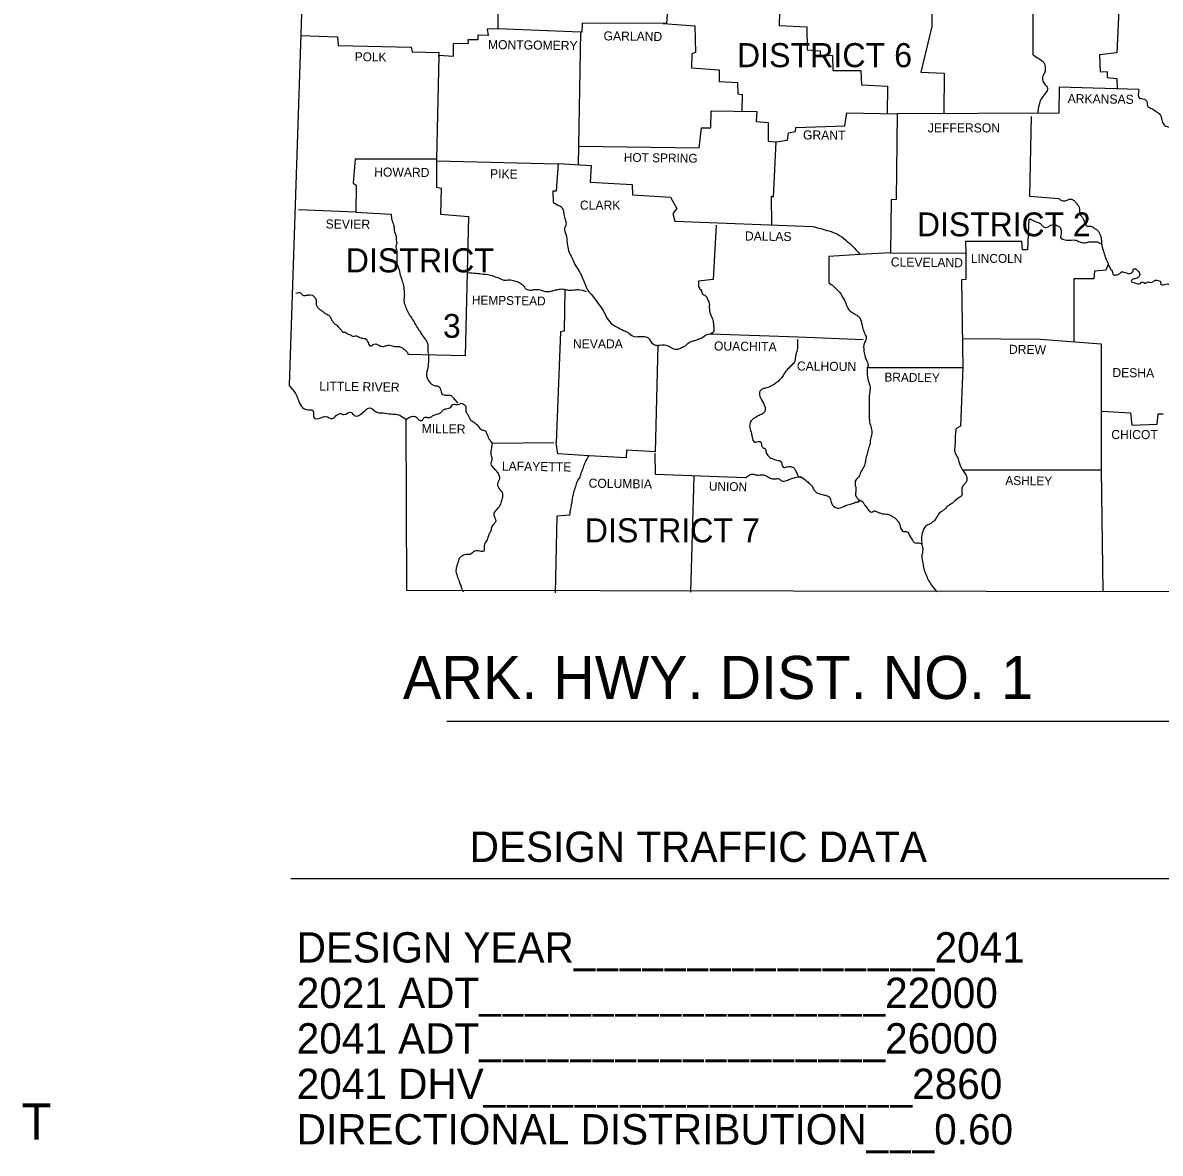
# Model space of a CAD drawing. Extents: x -117616 to 64730, y 54117 to 789866.
# Drawn here: x 63874 to 64437, y 55167 to 55726 of the extents above; entities that cross this region are included whole.
import ezdxf

# ---------------------------------------------------------------- set-up
doc = ezdxf.new("R2010")
doc.units = 0
doc.layers.add('Default', color=7, linetype='Continuous')
doc.layers.add('R_Draft', color=7, linetype='Continuous')

msp = doc.modelspace()

# ---------------------------------------------------------------- linework, layer by layer
at = {"layer": 'Default'}
for p, q in [((64150.16, 55721.35), (64148.95, 55655.78)), ((64084.07, 55380.58), (64442.95, 55380.58))]:
    msp.add_line(p, q, dxfattribs=at)
for points in [[(63993.86, 56003.36), (64015.47, 55829.83), (64006.07, 55546.57)], [(64109.44, 55783.99), (64109.23, 55722.91), (64104.01, 55722.81), (64104.43, 55719.68), (64099.42, 55719.78), (64099.31, 55717.49), (64094.41, 55717.49), (64094.51, 55715.81), (64087.2, 55715.61), (64087.1, 55709.24), (64080, 55709.86), (64078.85, 55658.49), (64038.65, 55658.6), (64037.71, 55646.7), (64039.17, 55645.65), (64039.07, 55632.29), (64010.56, 55633.54)], [(64358.99, 55769.27), (64359.19, 55750.58), (64373.92, 55750.27), (64374.02, 55710.18)], [(64317.74, 55764.47), (64323.8, 55764.05), (64323.9, 55724.17), (64318.47, 55701.51), (64330.06, 55700.99), (64329.96, 55681.03)], [(64416.83, 55739.72), (64415.58, 55711.12), (64407.01, 55710.18), (64407.22, 55701.72), (64410.67, 55701.82), (64410.77, 55698.9), (64415.47, 55698.38), (64415.63, 55693.34)], [(64227.84, 55738.05), (64193.7, 55739.1), (64192.76, 55725.63), (64151, 55725.84), (64150.83, 55721.32)], [(64237.14, 55738.37), (64248.83, 55737.64), (64248.41, 55724.58), (64262.09, 55724.06), (64262.3, 55712.68), (64268.77, 55712.16), (64268.77, 55710.18), (64274.83, 55709.76), (64275.04, 55702.45), (64288.82, 55702.45), (64289.24, 55695.25), (64301.98, 55694.62), (64301.87, 55681.05)], [(64150.16, 55721.35), (64109.23, 55722.91)], [(64191.1, 55725.64), (64206.65, 55724.48), (64207.07, 55711.33), (64205.29, 55710.7), (64205.08, 55703.7), (64218.76, 55702.76), (64218.76, 55697.02), (64227.84, 55696.5), (64227.95, 55690.76), (64230.14, 55690.44), (64230.03, 55682.19)], [(64011.82, 55719.68), (64029.88, 55719.05), (64030.3, 55714.67), (64066.42, 55713.94), (64066.84, 55711.64), (64080, 55711.22), (64079.89, 55709.24)], [(64150.83, 55721.32), (64150.16, 55721.35)], [(64426.44, 55693.05), (64386.97, 55694.1), (64386.76, 55681.26), (64306.89, 55680.94)], [(64149.12, 55664.97), (64208.84, 55664.13), (64209.99, 55674.05), (64214.69, 55674.05), (64214.79, 55682.4), (64237.35, 55682.09), (64237.14, 55677.08), (64242.98, 55676.66), (64242.98, 55667.47), (64246.74, 55667.16), (64246.7, 55666.21)], [(64246.74, 55667.16), (64252.59, 55668), (64253.01, 55671.55), (64256.45, 55672.17), (64256.66, 55674.26), (64280.99, 55674.99), (64281.93, 55681.36), (64306.88, 55680.94)], [(64306.89, 55680.94), (64306.26, 55638.55), (64303.86, 55638.45), (64303.54, 55612.24)], [(64373.08, 55679.58), (64372.25, 55640.22), (64386.76, 55639.07)], [(64246.74, 55667.16), (64245.49, 55639.8), (64244.55, 55640.12), (64244.65, 55625.92)], [(64078.85, 55658.49), (64078.85, 55644.61), (64081.15, 55644.19), (64080.94, 55631.24), (64094.72, 55630.2), (64093.05, 55561.18), (64064.65, 55561.92)], [(64079.06, 55657.76), (64138.78, 55656.2)], [(64136.8, 55637.09), (64136.59, 55642.83), (64138.26, 55642.94), (64139.3, 55656.41), (64155.38, 55655.36), (64154.96, 55647.11), (64175.74, 55645.96), (64175.85, 55640.95), (64194.64, 55639.8), (64197.88, 55634.17), (64195.89, 55631.66), (64196.83, 55627.8), (64264.91, 55625.29)], [(64039.07, 55632.29), (64056.4, 55631.24)], [(64371.93, 55629.05), (64371.31, 55613.7), (64368.9, 55613.7), (64368.49, 55617.77), (64340.71, 55617.77), (64340.74, 55612.03)], [(64217.3, 55625.81), (64215.73, 55598.98), (64208.53, 55598.15)], [(64288.34, 55611.3), (64273.05, 55610.36), (64272.95, 55597.31)], [(64303.54, 55612.24), (64288.28, 55611.3)], [(64303.54, 55612.24), (64340.5, 55612.03)], [(64340.74, 55612.03), (64340.82, 55598.98), (64338.63, 55598.88), (64339.25, 55555.55)], [(64411.3, 55606.5), (64410.04, 55603.68), (64404.51, 55603.16), (64404.2, 55599.4), (64394.28, 55599.4), (64394.17, 55568.18)], [(64142.33, 55594.18), (64142.12, 55573.4), (64140.24, 55573.19), (64138.15, 55518.17)], [(64214.69, 55572.15), (64257.91, 55570.58), (64289.97, 55569.33)], [(64188.38, 55566.3), (64187.02, 55513.68), (64172.92, 55514.62), (64172.82, 55510.75), (64154.33, 55511.83)], [(64338.94, 55569.75), (64377.68, 55569.43), (64407.75, 55567.14)], [(64407.75, 55567.14), (64407.75, 55504.7), (64408.58, 55444.66)], [(64292.06, 55555.44), (64339.25, 55555.55)], [(64339.25, 55555.55), (64338.21, 55526.52), (64335.91, 55525.06)], [(64408.27, 55533.83), (64422.26, 55532.99), (64422.89, 55526.94), (64435.52, 55527.36), (64436.04, 55532.47), (64438.44, 55532.47)], [(64063.81, 55529.76), (64064.02, 55445.29), (64446.69, 55444.66)], [(64136.99, 55518.16), (64106.52, 55517.85)], [(64154.34, 55511.84), (64138.89, 55512.74), (64138.15, 55518.17)], [(64231.81, 55500.94), (64187.23, 55502.61), (64187.02, 55513.16)], [(64339.88, 55504.8), (64407.75, 55504.8)], [(64206.23, 55501.67), (64204.56, 55444.35)], [(64144.84, 55482.36), (64138.36, 55481.94), (64137.63, 55444.04)]]:
    msp.add_lwpolyline(points, dxfattribs=at)
for points in [[(64374.02, 55710.18), (64376.63, 55708.4), (64379.35, 55706.31), (64380.08, 55703.49), (64379.87, 55701.51), (64379.03, 55699.84), (64378.82, 55697.23), (64380.08, 55695.35), (64381.23, 55693.78), (64380.08, 55690.97), (64378.09, 55688.35), (64377.05, 55685.43), (64376.32, 55681.05)], [(64426.44, 55693.05), (64426.75, 55688.77), (64429.25, 55688.15), (64430.3, 55687), (64430.82, 55684.6), (64432.6, 55683.55), (64435, 55682.09), (64436.46, 55681.05), (64437.5, 55679.38), (64438.13, 55676.66), (64439.8, 55674.89), (64442.1, 55674.05), (64443.77, 55672.07), (64444.81, 55669.25), (64446.48, 55668), (64448.15, 55665.8), (64448.99, 55664.86), (64450.45, 55662.36), (64451.91, 55661.1), (64452.96, 55660.37), (64454.63, 55659.85), (64456.72, 55658.49), (64458.07, 55656.41), (64458.07, 55654.84), (64457.55, 55652.44), (64457.13, 55649.93), (64456.92, 55647.11), (64456.72, 55644.61), (64457.65, 55642.52), (64457.13, 55639.39), (64456.09, 55637.72), (64455.98, 55635.42), (64455.67, 55631.97), (64455.25, 55629.99), (64454.31, 55626.75), (64452.96, 55625.08)], [(64386.76, 55639.07), (64388.33, 55638.03), (64390.52, 55638.13), (64391.98, 55638.76), (64393.13, 55638.66), (64394.69, 55637.72), (64395.74, 55636.46), (64396.47, 55635.52), (64396.99, 55634.06), (64396.99, 55632.7), (64397.51, 55630.83), (64398.14, 55630.09), (64398.98, 55628.74), (64399.5, 55627.48), (64399.81, 55626.65), (64400.96, 55625.29), (64402, 55625.4), (64402.94, 55625.29), (64404.2, 55624.56), (64406.08, 55623.1), (64406.39, 55622.68), (64407.64, 55619.97), (64407.85, 55618.3), (64408.06, 55616.1), (64408.48, 55614.02), (64409.31, 55611.72), (64409.73, 55610.15), (64410.67, 55607.96), (64411.3, 55606.5), (64412.13, 55604.62), (64413.38, 55602.53), (64413.91, 55601.28), (64415.68, 55601.38), (64416.93, 55601.9), (64417.87, 55602.74), (64419.02, 55602.63), (64420.28, 55602.22), (64421.95, 55601.9), (64422.99, 55602.53), (64423.51, 55602.95), (64423.62, 55603.89), (64424.56, 55604.41), (64425.6, 55603.68), (64426.75, 55602.01), (64426.75, 55600.96), (64426.33, 55600.34), (64424.97, 55599.5), (64423.09, 55598.88), (64422.57, 55598.15), (64424.35, 55597.31), (64427.17, 55597.1), (64427.9, 55597.73), (64429.78, 55597.21), (64430.51, 55597.73), (64433.01, 55597.62), (64434.16, 55598.46), (64436.46, 55598.35), (64437.19, 55597.83), (64437.19, 55596.89), (64439.07, 55596.47), (64440.43, 55596.79), (64442.2, 55596.27), (64443.77, 55595.43), (64444.6, 55594.28), (64445.65, 55593.03), (64446.59, 55593.34), (64447.32, 55594.28), (64448.88, 55595.95), (64448.88, 55597), (64449.3, 55597.73), (64449.82, 55598.77)], [(64136.8, 55637.09), (64138.47, 55636.05), (64140.45, 55635.11), (64141.5, 55633.54), (64141.91, 55631.14), (64142.64, 55628.53), (64142.85, 55625.81), (64142.23, 55624.35), (64143.06, 55621.01), (64143.38, 55618.71), (64143.69, 55616), (64144.52, 55612.35), (64145.88, 55609.84), (64147.13, 55606.81), (64149.22, 55603.57), (64151, 55600.02), (64151.83, 55598.15), (64153.4, 55594.28), (64155.38, 55591.67), (64158.51, 55587.7), (64161.33, 55583.63), (64162.9, 55580.6), (64165.3, 55577.26), (64168.02, 55575.59), (64171.46, 55573.82), (64173.65, 55572.77), (64176.16, 55571), (64179.4, 55570.79), (64181.8, 55570.79), (64183.99, 55569.85), (64185.04, 55567.97), (64186.91, 55566.72), (64188.38, 55566.3)], [(64056.4, 55631.24), (64056.92, 55628.11), (64057.86, 55625.4), (64057.97, 55623.31), (64058.91, 55620.18), (64058.91, 55619.03), (64059.22, 55616.73), (64058.8, 55615.48), (64059.32, 55612.97), (64059.22, 55611.09), (64059.22, 55609.53), (64059.32, 55606.92), (64060.16, 55604.62), (64060.99, 55601.17), (64061.52, 55599.4), (64062.35, 55596.68), (64062.87, 55593.34), (64062.98, 55590.84), (64062.77, 55588.54), (64063.4, 55585.93), (64064.54, 55583.32), (64066.01, 55580.81), (64067.78, 55577.99), (64069.03, 55575.8), (64070.6, 55573.4), (64071.85, 55571.42), (64073.73, 55568.91), (64074.57, 55566.82), (64074.57, 55563.9), (64074.99, 55561.18), (64074.88, 55558.16), (64074.67, 55555.44), (64073.94, 55551.68), (64074.46, 55549.91), (64076.45, 55547.3), (64077.7, 55546.57), (64079.89, 55546.15), (64080.94, 55544.69), (64081.56, 55542.5), (64083.76, 55541.76), (64086.16, 55541.56), (64087.31, 55540.3), (64088.87, 55538.63), (64089.39, 55537.8)], [(64371.93, 55629.05), (64373.81, 55628.42), (64375.17, 55627.69), (64376.94, 55627.07), (64378.09, 55626.23), (64379.66, 55624.87), (64381.54, 55625.08), (64382.9, 55625.92), (64384.25, 55626.13), (64385.3, 55626.02), (64386.45, 55625.4), (64387.7, 55624.46), (64387.91, 55623.1), (64387.91, 55621.53), (64387.91, 55619.34), (64388.64, 55619.03), (64391.25, 55618.4), (64393.02, 55618.51), (64394.69, 55618.51), (64396.05, 55618.19), (64397.2, 55617.57), (64398.04, 55617.36), (64399.29, 55617.15), (64400.33, 55617.25), (64402.11, 55617.67), (64403.15, 55617.67), (64404.82, 55617.67), (64405.87, 55617.57), (64407.43, 55616.73)], [(64264.91, 55625.29), (64273.05, 55622.99), (64277.23, 55621.43), (64281.41, 55618.4), (64284.85, 55615.37), (64288.3, 55611.51)], [(64094.51, 55602.43), (64098.48, 55602.11), (64102.13, 55601.7), (64104.95, 55601.38), (64107.88, 55600.34), (64110.49, 55599.4), (64112.16, 55598.67), (64114.98, 55598.88), (64117.38, 55598.35), (64120.09, 55597.41), (64122.08, 55595.64), (64123.33, 55594.28), (64125.73, 55593.76), (64127.71, 55594.07), (64130.11, 55593.86), (64132.83, 55593.03), (64135.02, 55593.13), (64136.8, 55593.55), (64138.89, 55594.07), (64141.5, 55594.28), (64143.48, 55593.86), (64146.09, 55593.76), (64149.12, 55594.07), (64152.88, 55593.03)], [(64208.53, 55598.15), (64208.53, 55596.16), (64209.26, 55594.28), (64209.99, 55593.45), (64210.3, 55592.09), (64211.24, 55591.46), (64212.6, 55590.21), (64213.33, 55588.44), (64213.85, 55587.29), (64213.85, 55585.83), (64213.96, 55584.36), (64214.17, 55582.59), (64215.42, 55579.46), (64215.73, 55578.2), (64215.94, 55577.16), (64216.05, 55575.38), (64216.05, 55573.3), (64214.69, 55572.15)], [(64272.95, 55597.31), (64275.35, 55595.74), (64277.34, 55593.66), (64278.8, 55592.09), (64279.74, 55590.31), (64280.99, 55588.23), (64282.76, 55584.26), (64284.33, 55582.9), (64286.52, 55581.54), (64287.88, 55580.6), (64289.24, 55577.58), (64289.86, 55574.55), (64291.01, 55571.83), (64291.54, 55569.75), (64290.6, 55567.66), (64290.39, 55563.48), (64291.01, 55560.66), (64291.85, 55558.57), (64292.37, 55556.17), (64292.06, 55555.44)], [(64009.31, 55592.3), (64011.61, 55592.4), (64013.17, 55591.05), (64014.11, 55591.15), (64015.78, 55591.36), (64017.35, 55591.25), (64018.5, 55590.31), (64019.44, 55588.64), (64019.33, 55587.08), (64019.44, 55586.45), (64020.17, 55585.09), (64021.42, 55584.05), (64022.78, 55583.01), (64024.03, 55582.17), (64026.12, 55580.81), (64026.33, 55580.4), (64027.16, 55578.73), (64028.21, 55577.37), (64029.46, 55576.53), (64030.82, 55575.07), (64031.45, 55574.44), (64032.49, 55572.98), (64033.64, 55572.88), (64035.2, 55571.94), (64036.35, 55571.63), (64037.61, 55570.79), (64038.86, 55571.21), (64040.43, 55570.58), (64042.51, 55569.95), (64043.66, 55569.75), (64045.02, 55567.76), (64046.38, 55566.09), (64048.05, 55567.03), (64051.18, 55566.09), (64053.16, 55565.99), (64054.94, 55566.51), (64056.3, 55566.4), (64058.8, 55565.78), (64060.37, 55565.78), (64062.04, 55565.15), (64063.6, 55563.9), (64064.65, 55562.54), (64064.65, 55561.92)], [(64209.99, 55569.95), (64212.7, 55571.73), (64215.73, 55572.15)], [(64209.99, 55569.95), (64209.24, 55569.65), (64207.9, 55569.12), (64206.34, 55568.6), (64204.87, 55568.18), (64202.99, 55566.93), (64201.53, 55565.88), (64199.55, 55564.94), (64197.67, 55564.32), (64195.37, 55565.05), (64194.12, 55565.78), (64192.76, 55566.3), (64188.38, 55566.3)], [(64257.5, 55569.33), (64257.29, 55564.11), (64256.56, 55560.87), (64255.83, 55557.95), (64254.26, 55556.28), (64252.59, 55554.61), (64251.02, 55552.73), (64249.67, 55550.43), (64248.31, 55548.97), (64246.53, 55547.51), (64244.76, 55546.46), (64242.78, 55545.52), (64240.58, 55545), (64239.02, 55543.85), (64238.91, 55541.35), (64240.69, 55537.8), (64241.31, 55536.13), (64241.52, 55534.14), (64240.79, 55532.99), (64239.12, 55532.05), (64237.14, 55530.91), (64235.36, 55529.86), (64234.11, 55528.09), (64233.9, 55525.69), (64234.74, 55522.87), (64235.05, 55521.2), (64236.41, 55518.59), (64237.45, 55518.69), (64239.33, 55518.59), (64239.54, 55518.06), (64239.64, 55517.54), (64240.06, 55516.18), (64241.63, 55515.04), (64241.84, 55513.99), (64242.78, 55512.01), (64244.34, 55510.65), (64245.49, 55510.23), (64247.89, 55509.5), (64249.14, 55509.19), (64250.5, 55506.16), (64252.17, 55506.27), (64253.43, 55506.47), (64255.51, 55505.95), (64256.45, 55504.7), (64257.39, 55502.61), (64258.65, 55501.15), (64259.48, 55501.15)], [(64292.06, 55555.44), (64292.48, 55548.97), (64293.41, 55545.84), (64293.1, 55542.5), (64293, 55539.26), (64293, 55536.34), (64293, 55533.52), (64293, 55530.59), (64293.21, 55528.5), (64293.94, 55525.48), (64294.25, 55522.66), (64293.62, 55519.94), (64293.31, 55517.44), (64292.48, 55514.93), (64291.74, 55512.11), (64290.91, 55508.46), (64290.18, 55506.06), (64288.72, 55503.55), (64287.78, 55501.25), (64286.31, 55499.79), (64286.11, 55497.29), (64286.42, 55494.99), (64286.21, 55492.9), (64286.94, 55490.92), (64288.82, 55489.56)], [(64006.07, 55546.57), (64009.1, 55542.6), (64010.35, 55539.78), (64012.13, 55536.13), (64014.74, 55534.66), (64017.77, 55534.14), (64018.39, 55530.59), (64021.53, 55530.49), (64024.03, 55531.22), (64027.48, 55530.28), (64031.13, 55532.79), (64033.22, 55532.16), (64036.25, 55533.41), (64038.55, 55531.53), (64042.51, 55533.2), (64046.06, 55535.5), (64049.4, 55533.31), (64052.64, 55532.99), (64056.5, 55532.47), (64059.53, 55532.26), (64062.25, 55530.91), (64064.23, 55529.55), (64063.81, 55529.76)], [(64063.81, 55529.76), (64067.47, 55531.32), (64069.03, 55530.8), (64070.39, 55529.44), (64071.96, 55529.44), (64072.79, 55530.7), (64074.36, 55530.8), (64075.61, 55530.7), (64076.97, 55531.53), (64078.12, 55532.05), (64079.68, 55532.58), (64080.83, 55532.99), (64081.88, 55534.14), (64083.76, 55535.08), (64085.95, 55535.81), (64086.58, 55536.86), (64087.62, 55537.27), (64089.71, 55537.17), (64091.06, 55537.8), (64092.21, 55537.27), (64093.26, 55536.54), (64093.47, 55533.83), (64094.3, 55532.37), (64095.55, 55529.76), (64097.33, 55528.4), (64099, 55527.04), (64099.63, 55526.21), (64101.4, 55524.64), (64102.97, 55524.12), (64103.7, 55522.97), (64104.85, 55520.26), (64106.52, 55517.85)], [(64335.91, 55525.06), (64335.6, 55521.82), (64335.49, 55518.79), (64335.28, 55515.87), (64335.28, 55513.68), (64336.54, 55511.28), (64337.27, 55508.98), (64338, 55507), (64339.46, 55504.39), (64340.82, 55502.4), (64341.24, 55499.58), (64340.4, 55498.12), (64338.83, 55495.93), (64338.73, 55491.96), (64336.85, 55490.71), (64334.45, 55488.62), (64333.09, 55487.68), (64331.63, 55486.74), (64330.06, 55485.07), (64327.77, 55483.5), (64326.1, 55480.89), (64324.22, 55478.91), (64322.65, 55477.87), (64320.46, 55476.51), (64319.52, 55474.42), (64318.79, 55470.56), (64319.1, 55467.74), (64319.52, 55465.23), (64319, 55462.1), (64319.52, 55458.65), (64320.04, 55455.94), (64320.88, 55453.54), (64322.02, 55450.82), (64323.49, 55448.32), (64326.62, 55444.45)], [(64106.52, 55517.85), (64105.89, 55514.83), (64105.79, 55512.43), (64106.31, 55509.61), (64105.79, 55508.25), (64106.62, 55506.27), (64108.19, 55504.7), (64109.34, 55503.03), (64110.07, 55500.63), (64109.13, 55497.91), (64110.17, 55495.09), (64111.11, 55494.05), (64111.63, 55492.38), (64110.9, 55489.14), (64109.96, 55486.74), (64107.88, 55484.34), (64107.25, 55483.19), (64107.56, 55481.62), (64108.08, 55479.12), (64107.56, 55478.39), (64106.2, 55476.61), (64105.79, 55474.63), (64104.85, 55472.96), (64103.8, 55469.93), (64102.45, 55467.42), (64102.24, 55464.61), (64100.15, 55464.61), (64097.75, 55464.61), (64095.55, 55463.04), (64093.57, 55462.94), (64091.17, 55462), (64089.71, 55460.01), (64089.19, 55457.82), (64088.56, 55455.73), (64089.19, 55452.18), (64090.13, 55449.68), (64090.86, 55447.69), (64092.11, 55444.45)], [(64144.84, 55482.36), (64145.36, 55485.7), (64145.88, 55488.31), (64146.19, 55490.81), (64146.82, 55493.63), (64147.76, 55496.66), (64148.6, 55499.17), (64149.74, 55500.94), (64150.48, 55503.03), (64151.41, 55505.53), (64152.35, 55508.14), (64154.23, 55511.82)], [(64231.81, 55500.94), (64233.48, 55502.09), (64235.05, 55502.72), (64236.61, 55502.4), (64238.29, 55502.19), (64239.75, 55502.4), (64241.63, 55502.09), (64243.19, 55501.15), (64244.97, 55500.42), (64246.74, 55500.42), (64248.31, 55500.42), (64249.67, 55499.48), (64252.17, 55499.58), (64254.26, 55500.42), (64256.35, 55501.04), (64259.17, 55501.36), (64261.67, 55499.58), (64263.45, 55498.12), (64264.91, 55496.45), (64265.95, 55494.57), (64267.1, 55493.53), (64268.98, 55492.8), (64270.44, 55492.48), (64272.22, 55491.96), (64273.16, 55491.54), (64273.99, 55489.56), (64275.35, 55486.85), (64277.96, 55485.91), (64281.2, 55487.16), (64283.81, 55487.89), (64285.69, 55488.52), (64286.84, 55488.93), (64287.88, 55489.04), (64287.57, 55489.25), (64288.82, 55489.56), (64289.97, 55488.72), (64290.7, 55487.58), (64291.95, 55485.91), (64293.1, 55484.44), (64294.25, 55483.92), (64295.4, 55484.55), (64296.96, 55484.03), (64298.32, 55483.5), (64299.89, 55483.09), (64301.25, 55482.98), (64303.02, 55482.56), (64304.38, 55481.83), (64305.63, 55481.1), (64306.88, 55479.75), (64308.14, 55477.66), (64308.55, 55475.99), (64310.02, 55474.32), (64311.37, 55474.32), (64313.36, 55471.6), (64314.09, 55470.56), (64315.65, 55468.68), (64316.8, 55468.68), (64319, 55468.26)]]:
    msp.add_spline(points, degree=3, dxfattribs=at)
at = {"layer": 'R_Draft'}
msp.add_line((64006.91, 55302.74), (64472.09, 55302.74), dxfattribs=at)

# ---------------------------------------------------------------- texts
at = {"layer": 'Default'}
for s, height, rotation, p in [('MONTGOMERY', 4.49, 359.2944, (64104.33, 55713)), ('GARLAND', 4.49, 359.3658, (64161.54, 55717.28)), ('POLK', 4.384, 359.2152, (64038.44, 55707.04)), ('ARKANSAS', 4.489, 359.2678, (64391.14, 55686.27)), ('GRANT', 4.49, 359.4032, (64260.21, 55668.31)), ('HOT SPRING', 4.386, 359.2216, (64171.57, 55657.24)), ('HOWARD', 4.49, 359.5145, (64048.05, 55649.93)), ('PIKE', 4.489, 359.0452, (64105.37, 55649.1)), ('SEVIER', 4.49, 359.4271, (64024.03, 55624.25)), ('DALLAS', 4.489, 359.2462, (64231.5, 55618.3)), ('CLEVELAND', 4.49, 359.3377, (64303.65, 55605.45)), ('HEMPSTEAD', 4.384, 359.1885, (64096.39, 55586.66)), ('OUACHITA', 4.49, 359.2043, (64216.15, 55563.9)), ('DREW', 4.489, 359.2258, (64362.12, 55562.23)), ('CALHOUN', 4.49, 359.3634, (64257.18, 55553.98)), ('DESHA', 4.489, 359.3704, (64413.28, 55550.74)), ('LITTLE RIVER', 4.4903, 359.1697, (64020.9, 55544.06)), ('BRADLEY', 4.384, 359.1449, (64300.51, 55548.55)), ('MILLER', 4.489, 359.132, (64071.54, 55523.08)), ('LAFAYETTE', 4.489, 359.1839, (64111.22, 55504.49)), ('COLUMBIA', 4.489, 359.2125, (64154.13, 55496.03)), ('UNION', 4.386, 358.9584, (64213.64, 55494.57)), ('ASHLEY', 4.386, 359.2361, (64360.34, 55497.39))]:
    msp.add_text(s, height=height, rotation=rotation, dxfattribs=at).set_placement(p)
for s, height, p in [('DISTRICT 6', 11.903, (64227.53, 55704.02)), ('JEFFERSON', 4.49, (64322.02, 55671.75)), ('CLARK', 4.49, (64149.85, 55633.54)), ('DISTRICT 2', 11.798, (64316.64, 55620.37)), ('DISTRICT', 11.903, (64033.95, 55602.53)), ('LINCOLN', 4.385, (64343.32, 55607.23)), ('3', 11.8, (64082.09, 55570.16)), ('NEVADA', 4.49, (64146.4, 55564.94)), ('CHICOT', 4.49, (64412.76, 55520.05)), ('DISTRICT 7', 11.903, (64152.25, 55468.99)), ('  ARK. HWY. DIST. NO. 1', 21.2995, (64046.44, 55391.5)), ('T', 18, (63873.65, 55173.5))]:
    msp.add_text(s, height=height, dxfattribs=at).set_placement(p)
at = {"layer": 'R_Draft'}
for s, p in [('DESIGN TRAFFIC DATA', (64095.32, 55310.9)), ('DESIGN YEAR________________2041', (64009.74, 55261.13)), ('2021 ADT__________________22000', (64009.74, 55238.63)), ('2041 ADT__________________26000', (64009.74, 55216.13)), ('2041 DHV___________________2860', (64009.74, 55193.63)), ('DIRECTIONAL DISTRIBUTION___0.60', (64009.74, 55171.13))]:
    msp.add_text(s, height=15, dxfattribs=at).set_placement(p)

doc.saveas('drawing.dxf')
